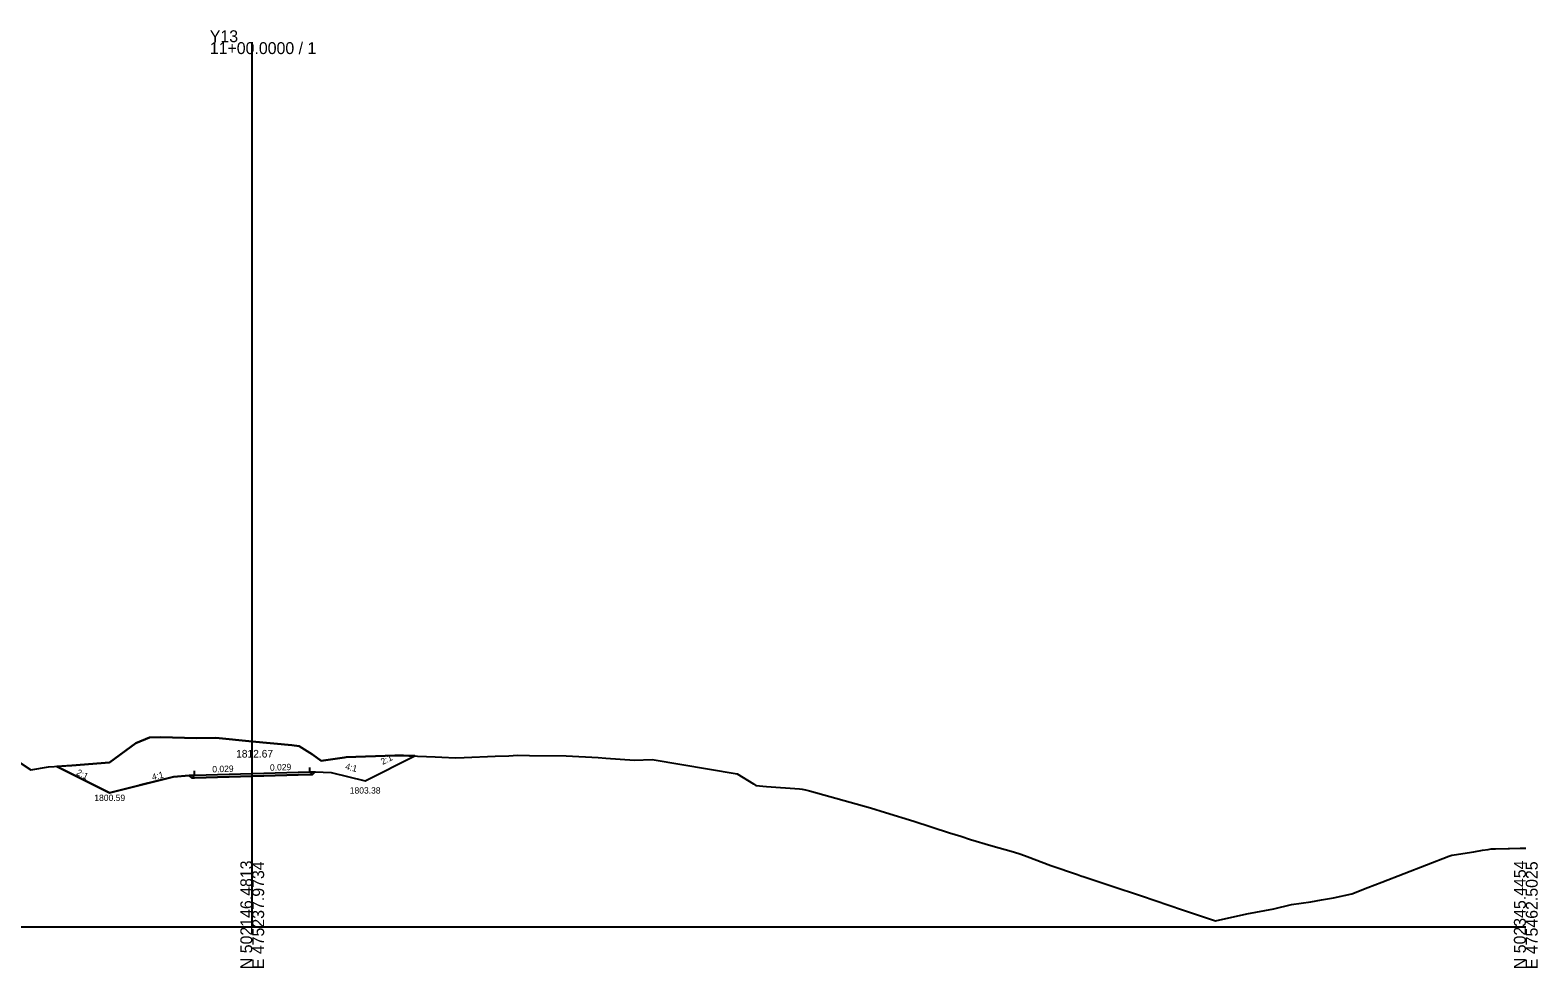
# Model space of a CAD drawing. Extents: x -126 to 503, y -10 to 2750.
# Drawn here: x 147.7 to 502.8, y 990.3 to 1211.3 of the extents above; entities that cross this region are included whole.
import ezdxf

# ---------------------------------------------------------------- set-up
doc = ezdxf.new("R2010")
doc.units = 0
for name, color, linetype in [('Exist Cross Section Cell', 7, 'Continuous'), ('Exist XS Center Line Elevation Label', 7, 'Continuous'), ('Exist XS Ground Line', 7, 'Continuous'), ('Prop XS Ditch Slope Text', 7, 'Continuous'), ('Prop XS Ditch Standard Text', 7, 'Continuous'), ('Prop XS Dump Level', 7, 'Continuous'), ('Prop XS Earthwork Shape', 7, 'Continuous'), ('Prop XS EOT Tick Mark', 7, 'Continuous'), ('Prop XS Finish Grade', 7, 'Continuous'), ('Prop XS Finish Grade Earthwork', 7, 'Continuous'), ('Prop XS Finish Grade Pavement', 7, 'Continuous'), ('Prop XS Hydro Typical Ditch Data', 7, 'Continuous'), ('Prop XS Pvmt Edge Slope', 7, 'Continuous'), ('Prop XS SE Text', 7, 'Continuous'), ('Prop XS Shoulder Borrow Shape', 7, 'Continuous'), ('Prop XS Side Slope Text', 7, 'Continuous'), ('Prop XS Subgrade Earthwork', 7, 'Continuous')]:
    doc.layers.add(name, color=color, linetype=linetype)

msp = doc.modelspace()

# ---------------------------------------------------------------- linework, layer by layer
at = {"layer": 'Exist Cross Section Cell'}
for p, q in [((200, 1000), (200, 1208.46)), ((-100, 1000), (200, 1000)), ((200, 1000), (500, 1000))]:
    msp.add_line(p, q, dxfattribs=at)
at = {"layer": 'Exist XS Ground Line'}
msp.add_lwpolyline([(142.99, 1040.21), (147.87, 1037), (152, 1037.68), (157.52, 1037.96), (166.38, 1038.67), (172.6, 1043.27), (175.8, 1044.59), (178.33, 1044.66), (186.97, 1044.44), (191.4, 1044.5), (200, 1043.67), (209.3, 1042.77), (211.05, 1042.55), (214.23, 1040.55), (216.2, 1039.07), (221.71, 1039.91), (222.11, 1039.97), (233.57, 1040.33), (234.87, 1040.37), (235.61, 1040.34), (236.88, 1040.31), (243.05, 1040.03), (244.67, 1039.96), (247.88, 1039.84), (249.93, 1039.91), (257.22, 1040.22), (260.47, 1040.3), (262.5, 1040.46), (265.32, 1040.36), (273.92, 1040.29), (281.45, 1039.86), (283.32, 1039.69), (290.04, 1039.26), (294.2, 1039.39), (314.22, 1036.03), (318.09, 1033.65), (318.6, 1033.3), (321.15, 1033.02), (328.88, 1032.46), (329.55, 1032.41), (330.31, 1032.28), (331.23, 1032.03), (345.63, 1028.03), (349.17, 1026.94), (355.86, 1024.9), (364.25, 1022.12), (366.88, 1021.31), (369.22, 1020.53), (373.97, 1019.11), (379.33, 1017.62), (381.05, 1017.11), (382.58, 1016.52), (388.14, 1014.45), (394.41, 1012.29), (395.22, 1012.03), (395.95, 1011.76), (402.31, 1009.64), (409.51, 1007.27), (419.1, 1003.95), (426.94, 1001.38), (434.27, 1003.03), (440.63, 1004.24), (444.82, 1005.21), (449.4, 1005.88), (451.91, 1006.32), (454.73, 1006.83), (458.99, 1007.78), (462.77, 1009.24), (466.08, 1010.54), (481.87, 1016.62), (482.55, 1016.83), (483.09, 1016.91), (487.77, 1017.65), (489.77, 1018.01), (491.11, 1018.22), (491.88, 1018.33), (492.51, 1018.35), (492.89, 1018.37), (495.82, 1018.46), (496.13, 1018.47), (498.66, 1018.53), (499.52, 1018.54), (500, 1018.54)], dxfattribs=at)
at = {"layer": 'Prop XS Dump Level'}
for p, q in [((186.42, 1035.75), (200, 1036.15)), ((200, 1036.15), (213.58, 1036.54))]:
    msp.add_line(p, q, dxfattribs=at)
at = {"layer": 'Prop XS Earthwork Shape'}
msp.add_lwpolyline([(218.59, 1036.38), (226.59, 1034.38), (238.31, 1040.24), (236.88, 1040.31), (235.61, 1040.34), (234.87, 1040.37), (233.57, 1040.33), (222.11, 1039.97), (221.71, 1039.91), (216.2, 1039.07), (214.23, 1040.55), (211.05, 1042.55), (209.3, 1042.77), (200, 1043.67), (191.4, 1044.5), (186.97, 1044.44), (178.33, 1044.66), (175.8, 1044.59), (172.6, 1043.27), (166.38, 1038.67), (157.52, 1037.96), (153.97, 1037.78), (166.36, 1031.59), (181.41, 1035.35), (185.14, 1035.65), (185.73, 1035.07), (186.42, 1035.09), (200, 1035.48), (213.58, 1035.87), (214.23, 1035.89), (214.84, 1036.5)], close=True, dxfattribs=at)
at = {"layer": 'Prop XS EOT Tick Mark'}
for p, q in [((213.58, 1036.54), (213.58, 1037.54)), ((186.42, 1035.75), (186.42, 1036.75))]:
    msp.add_line(p, q, dxfattribs=at)
at = {"layer": 'Prop XS Finish Grade'}
for p, q in [((186.42, 1035.75), (185.14, 1035.65)), ((213.58, 1036.54), (214.84, 1036.5))]:
    msp.add_line(p, q, dxfattribs=at)
at = {"layer": 'Prop XS Finish Grade Earthwork'}
for p, q in [((166.36, 1031.59), (153.97, 1037.78)), ((226.59, 1034.38), (238.31, 1040.24)), ((181.41, 1035.35), (166.36, 1031.59)), ((185.14, 1035.65), (181.41, 1035.35)), ((214.84, 1036.5), (218.59, 1036.38)), ((218.59, 1036.38), (226.59, 1034.38))]:
    msp.add_line(p, q, dxfattribs=at)
at = {"layer": 'Prop XS Finish Grade Pavement'}
for p, q in [((186.42, 1035.75), (200, 1036.15)), ((200, 1036.15), (213.58, 1036.54))]:
    msp.add_line(p, q, dxfattribs=at)
at = {"layer": 'Prop XS Hydro Typical Ditch Data'}
for p, q in [((166.36, 1031.59), (153.97, 1037.78)), ((226.59, 1034.38), (238.31, 1040.24)), ((181.41, 1035.35), (173.41, 1033.35)), ((218.59, 1036.38), (226.59, 1034.38))]:
    msp.add_line(p, q, dxfattribs=at)
at = {"layer": 'Prop XS Pvmt Edge Slope'}
for p, q in [((186.42, 1035.75), (185.73, 1035.07)), ((213.58, 1036.54), (214.23, 1035.89))]:
    msp.add_line(p, q, dxfattribs=at)
at = {"layer": 'Prop XS Shoulder Borrow Shape'}
for points in [[(186.42, 1035.75), (185.14, 1035.65), (185.73, 1035.07)], [(213.58, 1036.54), (214.84, 1036.5), (214.23, 1035.89)]]:
    msp.add_lwpolyline(points, close=True, dxfattribs=at)
at = {"layer": 'Prop XS Subgrade Earthwork'}
for p, q in [((185.73, 1035.07), (185.14, 1035.65)), ((186.42, 1035.09), (185.73, 1035.07)), ((200, 1035.48), (186.42, 1035.09)), ((213.58, 1035.87), (200, 1035.48)), ((213.58, 1035.87), (214.23, 1035.89)), ((214.23, 1035.89), (214.84, 1036.5))]:
    msp.add_line(p, q, dxfattribs=at)

# ---------------------------------------------------------------- texts
at = {"layer": 'Exist Cross Section Cell'}
for s, p in [('Y13', (190, 1208.46)), ('11+00.0000 / 1', (190, 1205.66))]:
    msp.add_text(s, height=2.8, dxfattribs=at).set_placement(p)
for s, p in [('N 502146.4813', (200, 990)), ('E 475237.9734', (202.8, 990)), ('N 502345.4454', (500, 990)), ('E 475462.5025', (502.8, 990))]:
    msp.add_text(s, height=2.8, rotation=90, dxfattribs=at).set_placement(p)
at = {"layer": 'Exist XS Center Line Elevation Label'}
msp.add_text('1812.67', height=1.8, dxfattribs=at).set_placement((196.2, 1039.87))
at = {"layer": 'Prop XS Ditch Slope Text'}
for rotation, p in [(345.9702, (221.8, 1037.13)), (14.0274, (176.55, 1034.5))]:
    msp.add_text('4:1', height=1.5, rotation=rotation, dxfattribs=at).set_placement(p)
at = {"layer": 'Prop XS Ditch Standard Text'}
for s, p in [('1800.59', (162.8, 1029.63)), ('1803.38', (222.97, 1031.38))]:
    msp.add_text(s, height=1.5, dxfattribs=at).set_placement(p)
at = {"layer": 'Prop XS Dump Level'}
for p in [(181.41, 1035.31), (218.59, 1036.34)]:
    msp.add_text('Case1', height=0.04, dxfattribs=at).set_placement(p)
at = {"layer": 'Prop XS SE Text'}
for p in [(190.61, 1036.37), (204.19, 1036.77)]:
    msp.add_text('0.029', height=1.5, rotation=1.6607, dxfattribs=at).set_placement(p)
at = {"layer": 'Prop XS Side Slope Text'}
for rotation, p in [(333.4501, (158.42, 1035.88)), (26.5542, (230.72, 1038.12))]:
    msp.add_text('2:1', height=1.5, rotation=rotation, dxfattribs=at).set_placement(p)

doc.saveas('drawing.dxf')
